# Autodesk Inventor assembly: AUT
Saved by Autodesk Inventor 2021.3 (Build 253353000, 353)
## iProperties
Created: 2022-04
Part Number: AUT
Document SubType Name: Assembly
Designer: Administrator
Title: AUT v2
Author: Administrator
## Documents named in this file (2)
- c:\worker\convert-fusion-r02\tmp\job-1\395\output\files\7d0e6c27-0fe2-4eb9-8b40-b8eb99277e2a\2b45f6e7-6239-4965-927f-e9b119c5b76d.iam
- c:\worker\convert-fusion-r02\tmp\job-1\395\output\files\7d0e6c27-0fe2-4eb9-8b40-b8eb99277e2a\Component1.ipt
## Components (1 placed, 1 different names)
1. Component1:1
